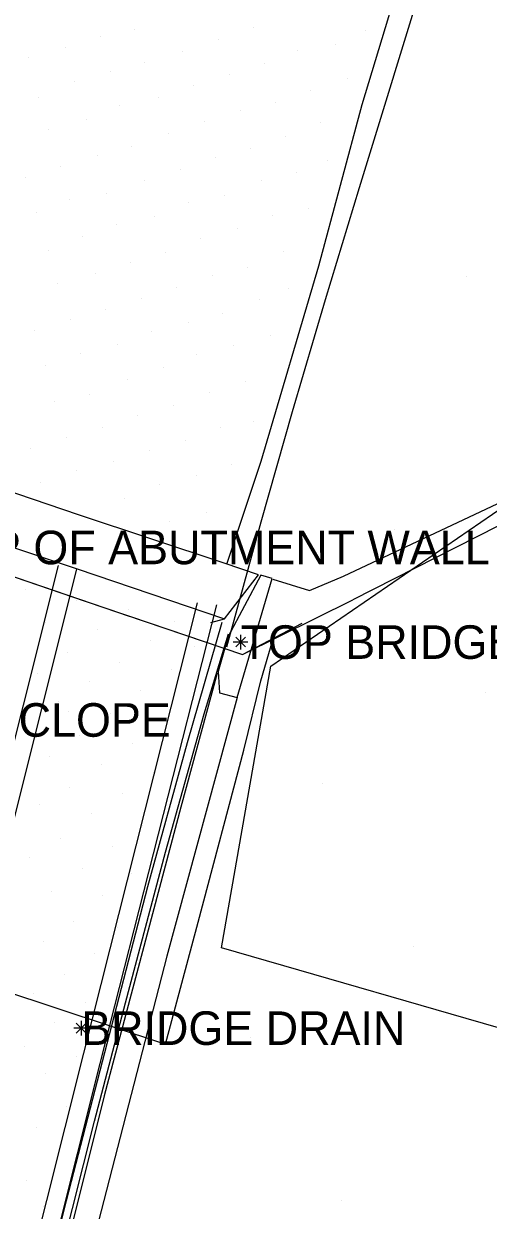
# Model space of a CAD drawing. Extents: x 1733582 to 1734070, y 467256 to 468256.
# Drawn here: x 1733875.9 to 1733900.8, y 467813.1 to 467876.7 of the extents above; entities that cross this region are included whole.
import ezdxf

# ---------------------------------------------------------------- set-up
doc = ezdxf.new("R2010")
doc.units = 0
for name, color, linetype in [('Default', 7, 'Continuous'), ('S_Bridge_Abutment_Bottom', 7, 'Continuous'), ('S_Bridge_Curb', 7, 'Continuous'), ('S_Bridge_Deck', 7, 'Continuous'), ('S_Bridge_ExpansionJoint', 7, 'Continuous'), ('S_Bridge_Parapet', 7, 'Continuous'), ('S_Bridge_Rail', 7, 'Continuous'), ('S_Bridge_Wingwall', 7, 'Continuous'), ('S_Ground_LevelString', 7, 'Continuous'), ('S_Ground_SpotElevation', 7, 'Continuous'), ('S_Guardrail_Beam', 7, 'Continuous'), ('S_Misc_MiscFeature', 7, 'Continuous'), ('S_Misc_MiscItems', 7, 'Continuous'), ('S_Roadway_Edge_Pavement', 7, 'Continuous'), ('S_Text', 7, 'Continuous'), ('S_Trees_Bush_Line', 7, 'Continuous')]:
    doc.layers.add(name, color=color, linetype=linetype)

# ---------------------------------------------------------------- blocks, each defined once
blk = doc.blocks.new('POINT_DISPLAY')
at = {"layer": 'Default'}
blk.add_line((0, 0), (0, 0), dxfattribs=at)

msp = doc.modelspace()

# ---------------------------------------------------------------- linework, layer by layer
at = {"layer": 'S_Bridge_Abutment_Bottom'}
for points in [[(1733850.373, 467860.35), (1733853.263, 467854.563), (1733867.149, 467849.901), (1733879.209, 467845.764), (1733887.663, 467842.899), (1733893.569, 467845.839)], [(1733852.42, 467856.251), (1733850.086, 467849.997), (1733848.643, 467844.425), (1733847.351, 467839.52), (1733846.701, 467837.477), (1733845.911, 467834.929), (1733857.447, 467830.97), (1733871.792, 467825.895), (1733883.518, 467822.024), (1733885.278, 467828.551), (1733887.725, 467837.781), (1733888.645, 467841.491), (1733889.276, 467843.701)]]:
    msp.add_lwpolyline(points, dxfattribs=at)
at = {"layer": 'S_Bridge_Curb'}
msp.add_lwpolyline([(1733850.525, 467652.736), (1733851.676, 467663.636), (1733852.883, 467674.082), (1733854.262, 467685.548), (1733855.565, 467694.75), (1733856.845, 467703.748), (1733858.974, 467717.399), (1733861.233, 467731.524), (1733863.482, 467743.881), (1733865.283, 467752.922), (1733867.113, 467762.582), (1733868.83, 467770.933), (1733871.654, 467784.015), (1733874.05, 467794.414), (1733876.107, 467803.265), (1733877.952, 467810.863), (1733879.709, 467817.89), (1733881.379, 467824.23), (1733883.522, 467832.303), (1733885.6, 467839.734), (1733886.897, 467844.023)], dxfattribs=at)
at = {"layer": 'S_Bridge_Deck'}
msp.add_line((1733885.952, 467844.629), (1733886.695, 467844.816), dxfattribs=at)
msp.add_lwpolyline([(1733886.549, 467844.629), (1733884.683, 467838.178), (1733882.551, 467830.444), (1733878.067, 467813.135), (1733874.221, 467797.292), (1733871.125, 467783.729), (1733866.753, 467762.871), (1733863.994, 467749.165), (1733860.716, 467731.07), (1733858.373, 467716.77), (1733855.935, 467700.728), (1733853.766, 467684.771), (1733851.796, 467669.015), (1733850.46, 467656.5), (1733850.135, 467652.683), (1733850.236, 467652.213)], dxfattribs=at)
at = {"layer": 'S_Bridge_ExpansionJoint'}
for points in [[(1733888.515, 467847.187), (1733886.678, 467847.805), (1733878.85, 467850.396), (1733871.551, 467852.887), (1733863.133, 467855.581), (1733854.845, 467858.314)], [(1733888.515, 467847.187), (1733886.678, 467847.805), (1733878.85, 467850.396), (1733871.551, 467852.887), (1733863.133, 467855.581), (1733854.845, 467858.314), (1733855.12, 467855.138), (1733863.226, 467852.582), (1733871.238, 467850.017), (1733878.782, 467847.499), (1733886.695, 467844.816), (1733888.515, 467847.187)]]:
    msp.add_lwpolyline(points, dxfattribs=at)
at = {"layer": 'S_Bridge_Parapet'}
msp.add_lwpolyline([(1733888.638, 467847.157), (1733886.892, 467843.865), (1733886.343, 467841.996), (1733886.416, 467840.857), (1733887.367, 467840.604), (1733889.239, 467846.98), (1733888.638, 467847.157)], dxfattribs=at)
at = {"layer": 'S_Bridge_Rail'}
msp.add_lwpolyline([(1733886.303, 467841.899), (1733884.339, 467834.722), (1733880.236, 467819.247), (1733876.383, 467803.848), (1733872.741, 467788.157), (1733869.344, 467772.479), (1733866.194, 467756.807), (1733863.147, 467741.167), (1733860.402, 467725.353), (1733857.873, 467709.488), (1733855.573, 467693.7), (1733853.508, 467677.718), (1733851.616, 467661.907), (1733850.883, 467654.795)], dxfattribs=at)
at = {"layer": 'S_Bridge_Wingwall'}
msp.add_line((1733893.064, 467847.099), (1733904.251, 467852.378), dxfattribs=at)
for points in [[(1733904.251, 467852.378), (1733904.697, 467851.491), (1733893.569, 467845.839)], [(1733889.275, 467846.946), (1733891.249, 467846.341), (1733893.064, 467847.099)]]:
    msp.add_lwpolyline(points, dxfattribs=at)
at = {"layer": 'S_Ground_LevelString'}
msp.add_lwpolyline([(1733852.42, 467856.251), (1733850.086, 467849.997), (1733848.643, 467844.425), (1733847.351, 467839.52), (1733846.701, 467837.477), (1733845.911, 467834.929), (1733857.447, 467830.97), (1733871.792, 467825.895), (1733883.518, 467822.024), (1733885.278, 467828.551), (1733887.725, 467837.781), (1733888.645, 467841.491), (1733889.276, 467843.701)], dxfattribs=at)
at = {"layer": 'S_Guardrail_Beam'}
msp.add_lwpolyline([(1733917.769, 467926.149), (1733916.624, 467925.086), (1733914.826, 467923.029), (1733913.076, 467920.699), (1733911.467, 467917.99), (1733910.12, 467915.13), (1733905.559, 467903.511), (1733903.456, 467897.694), (1733901.373, 467891.723), (1733899.455, 467885.825), (1733897.622, 467879.976), (1733893.915, 467867.918), (1733892.096, 467861.914), (1733890.319, 467855.919), (1733888.634, 467850.008), (1733886.803, 467843.305)], dxfattribs=at)
at = {"layer": 'S_Misc_MiscFeature'}
for points in [[(1733851.612, 467857.638), (1733853.196, 467854.581), (1733859.544, 467852.463), (1733859.587, 467852.455), (1733866.898, 467850.008), (1733866.968, 467849.988), (1733874.19, 467847.475), (1733874.253, 467847.466), (1733881.575, 467844.967), (1733881.654, 467844.95), (1733887.649, 467842.907), (1733890.85, 467844.587)], [(1733851.612, 467857.638), (1733853.196, 467854.581), (1733859.544, 467852.463), (1733859.587, 467852.455), (1733866.898, 467850.008), (1733866.968, 467849.988), (1733874.19, 467847.475), (1733874.253, 467847.466), (1733881.575, 467844.967), (1733881.654, 467844.95), (1733887.649, 467842.907), (1733890.85, 467844.587)], [(1733841.162, 467655.238), (1733844.601, 467681.503), (1733847.732, 467705.748), (1733850.338, 467725.565), (1733853.469, 467742.079), (1733855.705, 467753.836), (1733857.987, 467765.604), (1733860.885, 467780.409), (1733865.914, 467800.487), (1733872.136, 467825.216), (1733877.778, 467847.684)], [(1733878.753, 467847.484), (1733873.086, 467824.941), (1733866.9, 467800.334), (1733861.829, 467780.055), (1733858.912, 467765.093), (1733856.608, 467753.207), (1733854.359, 467741.368), (1733851.322, 467725.26), (1733848.676, 467705.17), (1733845.544, 467680.934), (1733842.168, 467654.979)], [(1733848.559, 467652.836), (1733852.024, 467679.791), (1733855.066, 467703.463), (1733857.598, 467722.922), (1733860.883, 467740.131), (1733863.02, 467751.281), (1733865.314, 467763.253), (1733868.31, 467778.566), (1733873.148, 467797.76), (1733879.142, 467821.53), (1733885.249, 467845.685)], [(1733849.555, 467652.651), (1733852.726, 467677.347), (1733855.925, 467702.233), (1733858.601, 467722.747), (1733863.855, 467750.228), (1733866.106, 467762.026), (1733869.19, 467777.948), (1733873.963, 467796.905), (1733880.016, 467820.978), (1733886.27, 467845.573)], [(1733887.367, 467840.604), (1733883.605, 467826.737), (1733879.636, 467811.346), (1733877.727, 467803.516), (1733874.188, 467788.265), (1733870.678, 467772.276), (1733867.49, 467756.558), (1733864.467, 467740.84), (1733861.741, 467725.141), (1733859.155, 467709.272), (1733856.917, 467693.32), (1733854.838, 467677.445), (1733853.015, 467661.799), (1733852.333, 467655.629)]]:
    msp.add_lwpolyline(points, dxfattribs=at)
at = {"layer": 'S_Misc_MiscItems'}
for p, q in [((1733887.944, 467843.572), (1733887.158, 467843.572)), ((1733887.813, 467843.31), (1733887.289, 467843.834)), ((1733887.813, 467843.834), (1733887.289, 467843.31)), ((1733887.551, 467843.965), (1733887.551, 467843.179)), ((1733879.265, 467822.613), (1733878.741, 467823.137)), ((1733879.265, 467823.137), (1733878.741, 467822.613)), ((1733879.003, 467823.268), (1733879.003, 467822.482)), ((1733879.396, 467822.875), (1733878.61, 467822.875))]:
    msp.add_line(p, q, dxfattribs=at)
at = {"layer": 'S_Roadway_Edge_Pavement'}
msp.add_lwpolyline([(1733886.814, 467847.747), (1733888.655, 467853.28), (1733891.748, 467863.741), (1733894.081, 467872.4), (1733896.996, 467882.033), (1733899.763, 467891.081), (1733902.19, 467897.233), (1733906.265, 467907.958), (1733909.558, 467915.947), (1733911.209, 467921.127), (1733913.596, 467927.782), (1733917.17, 467937.649), (1733920.601, 467948.44), (1733924.184, 467959.583), (1733929.14, 467973.94), (1733935.129, 467992.823), (1733938.847, 468003.699), (1733940.839, 468009.946)], dxfattribs=at)
at = {"layer": 'S_Trees_Bush_Line'}
msp.add_lwpolyline([(1734042.828, 467779.075), (1733971.317, 467805.697), (1733945.175, 467813.691), (1733934.958, 467813.533), (1733902.996, 467822.422), (1733886.522, 467827.184), (1733889.177, 467842.281), (1733906.698, 467854.289), (1733924.418, 467873.588), (1733941.988, 467893.873)], dxfattribs=at)

# ---------------------------------------------------------------- block references
at = {"layer": 'S_Ground_SpotElevation'}
for p in [(1733888.221, 467876.536), (1733880.018, 467876.039), (1733881.881, 467876.423), (1733886.348, 467875.892), (1733894.237, 467876.372), (1733878.136, 467875.442), (1733884.462, 467875.249), (1733890.621, 467875.304), (1733892.66, 467875.62), (1733876.175, 467874.889), (1733882.414, 467874.63), (1733880.567, 467874.153), (1733886.959, 467873.989), (1733888.851, 467874.595), (1733878.639, 467873.614), (1733885.004, 467873.401), (1733893.283, 467873.805), (1733876.706, 467872.754), (1733883.126, 467872.777), (1733891.3, 467873.131), (1733881.056, 467872.343), (1733887.531, 467872.099), (1733889.424, 467872.504), (1733879.286, 467871.588), (1733885.617, 467871.505), (1733891.832, 467871.443), (1733877.261, 467871.064), (1733883.701, 467870.841), (1733881.704, 467870.155), (1733889.948, 467870.681), (1733879.878, 467869.637), (1733886.223, 467869.549), (1733888.069, 467870.046), (1733877.87, 467869.069), (1733884.307, 467868.914), (1733892.22, 467869.371), (1733876.028, 467868.485), (1733882.393, 467868.319), (1733888.684, 467868.327), (1733890.559, 467868.741), (1733880.334, 467867.62), (1733878.397, 467867.292), (1733884.785, 467867.155), (1733886.703, 467867.534), (1733876.594, 467866.58), (1733882.959, 467866.397), (1733889.254, 467866.422), (1733891.181, 467866.801), (1733880.904, 467865.938), (1733887.373, 467865.767), (1733879.062, 467865.311), (1733885.405, 467865.185), (1733877.234, 467864.593), (1733883.551, 467864.474), (1733889.856, 467864.494), (1733881.629, 467863.905), (1733879.751, 467863.313), (1733886.044, 467863.22), (1733887.946, 467863.665), (1733899.689, 467863.199), (1733877.731, 467862.803), (1733884.126, 467862.593), (1733890.129, 467862.522), (1733882.246, 467862.002), (1733888.559, 467861.916), (1733880.317, 467861.41), (1733878.426, 467860.858), (1733884.746, 467860.712), (1733886.559, 467861.166), (1733876.511, 467860.286), (1733882.752, 467860.23), (1733889.157, 467859.988), (1733880.925, 467859.531), (1733887.173, 467859.458), (1733878.959, 467859.07), (1733885.198, 467858.974), (1733877.076, 467858.428), (1733883.403, 467858.272), (1733881.473, 467857.654), (1733887.809, 467857.529), (1733879.462, 467856.863), (1733885.892, 467856.961), (1733877.564, 467856.477), (1733883.969, 467856.242), (1733882.033, 467855.741), (1733880.169, 467855.086), (1733886.471, 467855.064), (1733888.235, 467855.394), (1733878.234, 467854.527), (1733884.576, 467854.385), (1733876.301, 467853.96), (1733882.672, 467853.846), (1733880.753, 467853.257), (1733887.049, 467853.068), (1733878.732, 467852.78), (1733885.185, 467852.503), (1733876.816, 467852.111), (1733883.218, 467852.022), (1733881.306, 467851.263), (1733885.744, 467850.497), (1733883.737, 467850.033), (1733895.818, 467849.597), (1733876.006, 467846.381), (1733878.765, 467845.827), (1733881.567, 467845.341), (1733877.11, 467844.621), (1733879.879, 467844.274), (1733883.989, 467844.668), (1733882.729, 467843.675), (1733878.293, 467843.034), (1733885.107, 467843.326), (1733881.031, 467842.475), (1733876.651, 467841.902), (1733883.821, 467842.085), (1733879.448, 467841.475), (1733882.176, 467840.991), (1733877.786, 467840.361), (1733900.683, 467840.86), (1733878.344, 467839.867), (1733880.57, 467839.737), (1733876.126, 467839.02), (1733883.304, 467839.392), (1733878.919, 467838.588), (1733881.75, 467838.137), (1733877.289, 467837.453), (1733880.097, 467836.994), (1733882.872, 467836.605), (1733891.946, 467835.995), (1733878.36, 467835.752), (1733881.213, 467835.468), (1733876.745, 467834.849), (1733879.543, 467834.367), (1733882.308, 467833.757), (1733877.919, 467833.028), (1733876.25, 467831.999), (1733880.703, 467832.589), (1733879.088, 467831.46), (1733881.714, 467831.168), (1733883.209, 467831.13), (1733877.427, 467830.178), (1733880.14, 467830.008), (1733878.594, 467828.6), (1733880.944, 467828.26), (1733876.982, 467827.497), (1733896.811, 467827.258), (1733879.699, 467826.882), (1733878.088, 467825.774), (1733876.442, 467824.708), (1733879.214, 467824.249), (1733877.578, 467823.197), (1733875.951, 467821.882), (1733888.074, 467822.393), (1733878.736, 467821.378), (1733877.078, 467820.426), (1733878.223, 467818.681), (1733876.618, 467817.536), (1733879.337, 467817.528), (1733877.726, 467815.843), (1733876.083, 467814.689), (1733892.939, 467813.656), (1733876.979, 467813.308)]:
    msp.add_blockref('POINT_DISPLAY', p, dxfattribs=at)

# ---------------------------------------------------------------- texts
at = {"layer": 'S_Text'}
for s, p in [('TOP OF ABUTMENT WALL', (1733870.823, 467847.746)), ('TOP BRIDGE WALL', (1733887.551, 467842.672)), ('CONC CLOPE', (1733867.891, 467838.498)), ('BRIDGE DRAIN', (1733879.003, 467821.975))]:
    msp.add_text(s, height=1.8, dxfattribs=at).set_placement(p)

doc.saveas('drawing.dxf')
